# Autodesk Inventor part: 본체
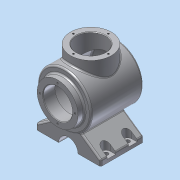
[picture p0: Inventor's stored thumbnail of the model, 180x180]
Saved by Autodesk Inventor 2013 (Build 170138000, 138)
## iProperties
Created: 2017-04
Part Number: 본체
Material: 알루미늄 6061
Document SubType Name: Modeling
Designer: narae
Density: 2.71 g/cm^3
Mass: 1670.76 g
Surface Area: 1066.86 cm^2
Volume: 616.516 cm^3
Author: narae
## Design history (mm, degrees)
sketch "스케치1"
  geometry: L1 (-50, 0)-(58, 0); L2 (-50, 0)-(-50, 50); L3 (-50, 50)-(46.336, 50); A1 r 113 centre (-55, 0) between (58, 0) and (46.336, 50); 2 further points
  constraints: 6 end point, 2 horizontal alignment, 2 perpendicular, 2 point on circle, 1 centre point, 1 horizontal, 1 midpoint, 1 point on line
  dimensions: "d0" = 108 distance of L1.end L1.start; "d1" = 50 distance of point (0, 0) L1.start; "d2" = 100 diameter of L3 L1; "d3" = 113 radius of A1
revolve "회전1" sketch "스케치1" stored, may be unused: angle "d4" = 90 deg
feature "쉘1" dims "d5" = 10
sketch "스케치2"
  geometry: C1 r 50 at (0, 0) reference; C2 r 38 at (0, 0)
  constraints: 1 centre point, 1 coincident
  dimensions: "d6" = 76 diameter of C2
extrude "돌출1" join sketch "스케치2" distance "d7" = 12; taper "d8" = 0 deg
sketch "스케치3"
  geometry: C1 r 38 at (0, 0) reference
hole "구멍1" sketch "스케치3" at (0, 0) diameter "d9" = 54; stored, may be unused: countersink angle "d13" = 90 deg, drill point angle "d15" = 0 deg; dims "d10" = 6, "d11" = 4, "d12" = 2, "d14" = 22
fillet "모깎기1" dims "d16" = 3
sketch "스케치4"
  geometry: C1 r 27 at (0, 0) reference; 1 further point
  constraints: 1 vertical alignment
  dimensions: "d17" = 32.5 distance of point (0, 32.5) C1.centre
hole "구멍2" sketch "스케치4" at (0, 32.5) diameter "d18" = 3.242; stored, may be unused: countersink angle "d22" = 90 deg, drill point angle "d24" = 118 deg; dims "d19" = 8, "d20" = 4, "d21" = 2, "d23" = 10
node "작업 평면1"
sketch "스케치5"
  geometry: C1 r 38 at (0, 0); 1 further point
  constraints: 1 centre point, 1 coincident
  dimensions: "d29" = 76 diameter of C1
extrude "돌출2" join sketch "스케치5" stored distance "d30" = 12; taper "d31" = 0 deg
sketch "스케치6"
  geometry: C1 r 38 at (0, 0) reference
hole "구멍3" sketch "스케치6" at (0, 0) diameter "d32" = 54; stored, may be unused: countersink angle "d36" = 90 deg, drill point angle "d38" = 0 deg; dims "d33" = 8, "d34" = 4, "d35" = 2, "d37" = 10
chamfer "모따기1" distance "d39" = 1; stored, may be unused: second distance "d40" = 2, angle "d41" = 45 deg
fillet "모깎기2" dims "d42" = 3
sketch "스케치7"
  geometry: C1 r 38 at (0, 0) reference; 1 further point
  constraints: 1 vertical alignment
  dimensions: "d43" = 32.5 distance of point (0, 32.5) C1.centre
hole "구멍4" sketch "스케치7" at (0, 32.5) diameter "d44" = 3.242; stored, may be unused: countersink angle "d48" = 90 deg, drill point angle "d50" = 118 deg; dims "d45" = 8, "d46" = 4, "d47" = 2, "d49" = 10
sketch "스케치8"
  geometry: L1 (-45.101, 21.584)-(-72, 60); L2 (-72, 60)-(-82, 60); L3 (-82, 60)-(-82, -60); L4 (-82, -60)-(-72, -60); L5 (-72, -60)-(-45.101, -21.584); A1 r 50 centre (0, 0) between (-45.101, 21.584) and (-45.101, -21.584) reference; 1 further point
  constraints: 10 end point, 2 equal length, 2 perpendicular, 2 point on circle, 1 horizontal
  dimensions: "d54" = 120 distance of L2.end L3.end; "d56" = 55 deg angle of L1 L2; "d58" = 10 distance of L1.end L2.end; "d59" = 82 distance from line of point (0, 0) L3; "d60" = 55 deg angle of L5 L4
extrude "돌출3" join sketch "스케치8" distance "d61" = 38; taper "d62" = 0 deg; dims "d83" = 42, "d84" = 0
sketch "스케치9"
  geometry: L1 (-60, -82)-(60, -82) reference; A1 r 18 centre (0, -82) between (18, -82) and (-18, -82); 1 further point
  constraints: 2 point on circle, 2 point on line, 1 centre point, 1 coincident, 1 midpoint
  dimensions: "d63" = 36 diameter of A1
extrude "돌출4" cut sketch "스케치9" stored distance "d64" = 80; taper "d65" = 0 deg
fillet "모깎기3" dims "d66" = 3
node "작업 평면2"
sketch "스케치10"
  geometry: L1 (-3, 42)-(-77, 42) reference; L2 (-12, 42)-(-12, 32); L3 (-28, 32)-(-28, 42); L4 (0, 0)-(0, 39) reference; A1 r 8 centre (-20, 32) between (-28, 32) and (-12, 32); 1 further point
  constraints: 4 end point, 2 perpendicular, 2 point on circle, 2 point on line, 2 tangent, 1 centre point
  dimensions: "d69" = 50 vertical distance of A1.centre point (-42, -18); "d70" = 16 distance between parallel lines of L2 L3; "d85" = 20 distance from line of A1.centre L4
extrude "돌출5" cut sketch "스케치10" stored distance "d71" = 80; taper "d72" = 0 deg
sketch "스케치11"
  geometry: A1 r 8 centre (20, -32) between (28, -32) and (12, -32) reference; 1 further point
hole "구멍5" sketch "스케치11" at (20, -32) diameter "d73" = 8; stored, may be unused: countersink angle "d77" = 90 deg, drill point angle "d79" = 0 deg; dims "d74" = 8, "d75" = 4, "d76" = 2, "d78" = 10
node "작업 평면3"
sketch "스케치12"
  geometry: 2 further points
  constraints: 1 coincident, 1 other
feature "엠보싱1" sketch "스케치12" dims "d81" = 0.5, "d82" = 0
node "솔리드1"
pattern_circular "원형 패턴1" dims angle "d26" = 360 deg
pattern_circular "원형 패턴2" dims angle "d52" = 360 deg
pattern_linear "직사각형 패턴1"
mirror "대칭3"
other parameters: "d28" = 65, "d67" = -6, "d80" = 58
